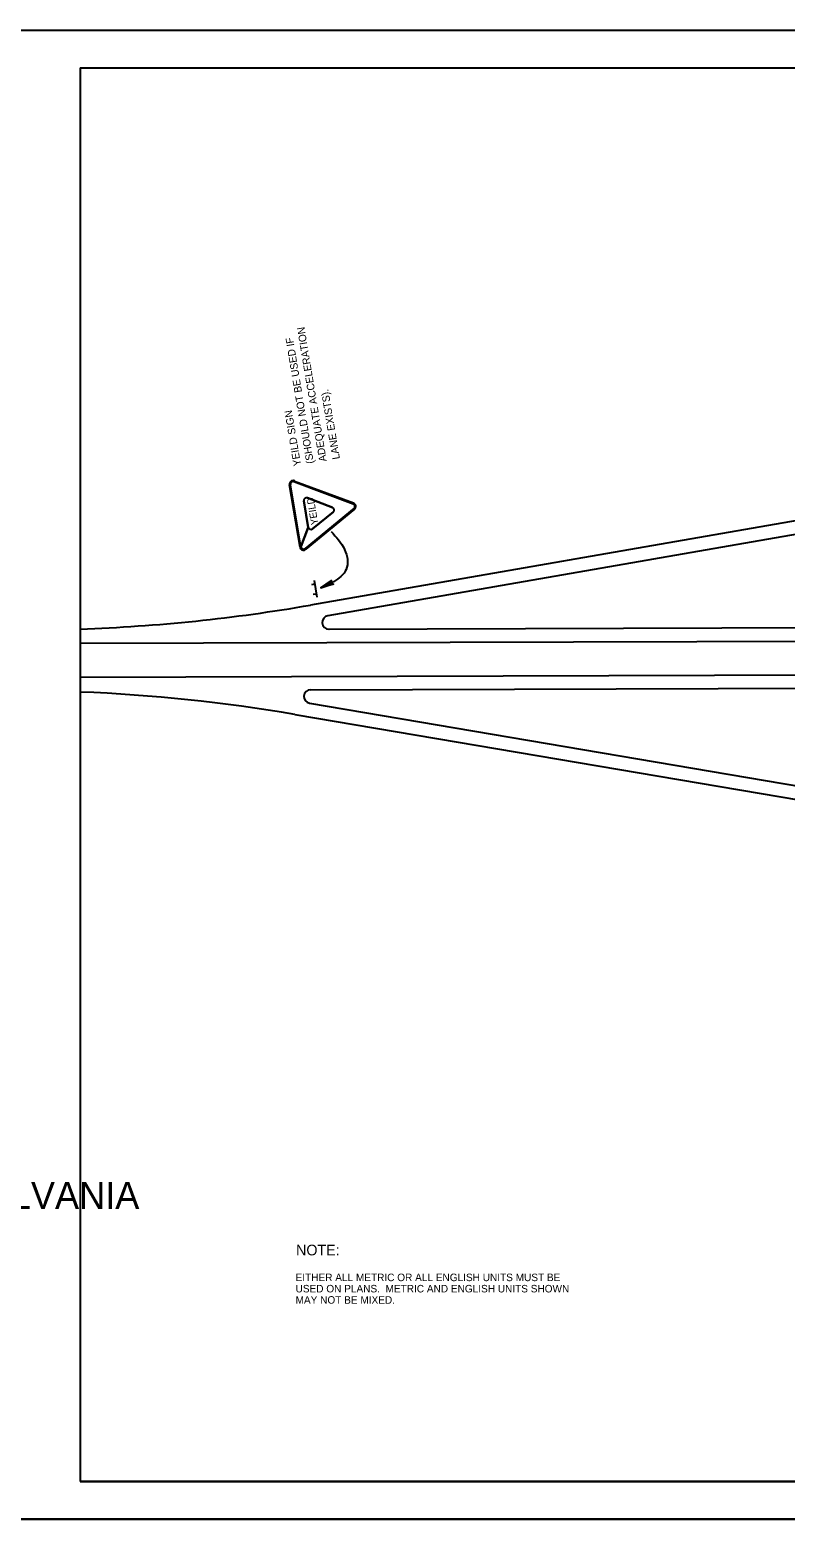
# Model space of a CAD drawing. Extents: x 640994 to 644422, y 298458 to 299646.
# Drawn here: x 642696 to 642998, y 299044 to 299646 of the extents above; entities that cross this region are included whole.
import ezdxf

# ---------------------------------------------------------------- set-up
doc = ezdxf.new("R2010")
doc.units = 0
for name, color, linetype in [('1', 7, 'Continuous'), ('2', 7, 'Continuous'), ('XCS-GRID-MIN', 7, 'Continuous')]:
    doc.layers.add(name, color=color, linetype=linetype)

msp = doc.modelspace()

# ---------------------------------------------------------------- linework, layer by layer
at = {"layer": '1'}
for p, q in [((642716.31, 299630.63), (643502.31, 299630.63)), ((642716.31, 299630.63), (642716.31, 299066.63)), ((643502.31, 299066.63), (642716.31, 299066.63)), ((642716.31, 299066.63), (643302.31, 299066.63))]:
    msp.add_line(p, q, dxfattribs=at)
at = {"layer": '2'}
for p, q in [((642804.06, 299439.38), (642799.81, 299464.25)), ((642804.31, 299439.5), (642800.19, 299464.25)), ((642804.31, 299439.5), (642800.19, 299464.25)), ((642801.56, 299465.5), (642825.19, 299456.63)), ((642801.56, 299465.5), (642825.19, 299456.63)), ((642801.81, 299465.75), (642825.31, 299457)), ((642807.31, 299447.25), (642805.56, 299457.88)), ((642805.56, 299457.88), (642807.31, 299447.25)), ((642806.94, 299459), (642816.94, 299455.25)), ((642816.94, 299455.25), (642806.94, 299459)), ((642825.56, 299454.88), (642806.06, 299438.88)), ((642825.56, 299454.88), (642806.06, 299438.88)), ((642825.69, 299454.5), (642806.31, 299438.5)), ((643014.31, 299452.13), (642808.19, 299416.25)), ((642817.31, 299453.5), (642808.94, 299446.63)), ((642808.94, 299446.63), (642817.31, 299453.5)), ((642810.56, 299453.25), (642810.56, 299453.25)), ((643052.94, 299453.38), (642815.06, 299412)), ((642807.31, 299447.25), (642804.31, 299439.5)), ((642804.31, 299439.5), (642807.31, 299447.25)), ((642807.31, 299447.25), (642804.31, 299439.5)), ((642804.31, 299439.5), (642807.31, 299447.25)), ((642807.31, 299447.25), (642804.31, 299439.5)), ((642804.31, 299439.5), (642807.31, 299447.25)), ((642808.94, 299446.63), (642808.94, 299446.63)), ((642809.94, 299424.63), (642808.56, 299424.38)), ((642809.69, 299426), (642810.69, 299419.38)), ((642810.56, 299420.63), (642809.19, 299420.5)), ((642815.56, 299406.63), (643084.94, 299407.5)), ((642716.31, 299401.01), (643085.69, 299402.13)), ((642716.31, 299387.51), (643087.81, 299388.63)), ((642808.19, 299382.5), (643088.56, 299383.25)), ((642801.94, 299372.63), (643086.31, 299324.5)), ((642807.81, 299377.13), (643077.81, 299331.38))]:
    msp.add_line(p, q, dxfattribs=at)
msp.add_lwpolyline([(642817.06, 299424.75), (642816.69, 299425), (642812.31, 299423.13), (642817.06, 299424.75), (642817.31, 299424.63), (642812.31, 299423.13), (642816.44, 299425.38), (642816.44, 299425.88), (642812.31, 299423.13), (642816.56, 299426.13), (642816.44, 299425.88)], dxfattribs=at)
for centre, radius, start, end in [((642801.25, 299464.48), 1.42, 69.47476, 189.47477), ((642801.25, 299464.48), 1.04, 69.47474, 189.47477), ((642801.25, 299464.48), 1.04, 69.47474, 189.47477), ((642806.57, 299458.03), 1.04, 69.47484, 189.47477), ((642806.57, 299458.03), 1.04, 69.47484, 189.47477), ((642824.85, 299455.65), 1.42, 309.4748, 69.47474), ((642816.6, 299454.27), 1.04, 309.47478, 69.47476), ((642816.6, 299454.27), 1.04, 309.47478, 69.47476), ((642824.85, 299455.65), 1.04, 309.47478, 69.47476), ((642824.85, 299455.65), 1.04, 309.47478, 69.47476), ((642808.33, 299447.46), 1.04, 189.47477, 309.4747), ((642808.33, 299447.46), 1.04, 189.47477, 309.4747), ((642805.4, 299439.63), 1.42, 189.47477, 309.47478), ((642805.4, 299439.63), 1.04, 189.47477, 309.47481), ((642805.4, 299439.63), 1.04, 189.47477, 309.47481), ((642693.03, 300078.18), 671.87, 271.98542, 279.8697), ((642815.58, 299409.35), 2.69, 99.8697, 270.16828), ((642689.69, 298710.22), 671.88, 80.38309, 87.72887), ((642808.26, 299379.76), 2.69, 90.16834, 260.38309)]:
    msp.add_arc(centre, radius, start, end, dxfattribs=at)
msp.add_spline([(642816.41, 299445.57), (642821.81, 299438.38), (642822.44, 299430.5), (642817.35, 299425.56), (642812.31, 299423.13)], degree=3, dxfattribs=at)
at = {"layer": 'XCS-GRID-MIN'}
for points in [[(642676.31, 299645.63), (643517.31, 299645.63), (643517.31, 299051.63), (642676.31, 299051.63)], [(642676.31, 299051.63), (643517.31, 299051.63), (643517.31, 298457.63), (642676.31, 298457.63)]]:
    msp.add_lwpolyline(points, close=True, dxfattribs=at)

# ---------------------------------------------------------------- texts
at = {"layer": '1'}
msp.add_text('COMMONWEALTH OF PENNSYLVANIA', height=10.7828, dxfattribs=at).set_placement((642473.9, 299175.36))
at = {"layer": '2'}
for s, height, rotation, p in [('ADEQUATE ACCELERATION', 3, 99.47488, (642814.69, 299473.75)), ('(SHOULD NOT BE USED IF', 3, 99.47488, (642809.56, 299472.88)), ('LANE EXISTS).', 3, 99.47488, (642819.94, 299474.63)), ('YEILD SIGN', 3, 99.47488, (642804.44, 299472)), ('YEILD', 2.859, 99.47477, (642811.31, 299448.5))]:
    msp.add_text(s, height=height, rotation=rotation, dxfattribs=at).set_placement(p)
for s, height, p in [('NOTE:', 4.25, (642802.45, 299156.82)), ('USED ON PLANS.  METRIC AND ENGLISH UNITS SHOWN', 3, (642802.24, 299142.04)), ('EITHER ALL METRIC OR ALL ENGLISH UNITS MUST BE', 3, (642802.24, 299146.54)), ('MAY NOT BE MIXED.', 3, (642802.24, 299137.54))]:
    msp.add_text(s, height=height, dxfattribs=at).set_placement(p)

doc.saveas('drawing.dxf')
